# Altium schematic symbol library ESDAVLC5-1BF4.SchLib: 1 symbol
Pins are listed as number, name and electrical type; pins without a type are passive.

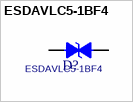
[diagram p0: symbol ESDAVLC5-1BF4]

## ESDAVLC5-1BF4
designator D?
footprint ST_0201B
pins: 1, 2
